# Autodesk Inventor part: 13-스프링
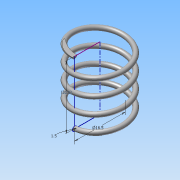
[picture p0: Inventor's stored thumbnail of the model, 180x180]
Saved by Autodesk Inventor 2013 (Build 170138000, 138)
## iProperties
Created: 2015-08
Part Number: 13-스프링
Material: 강철, 연강
Document SubType Name: Modeling
Designer: Administrator
Mass: 2.84502 g
Surface Area: 9.78731 cm^2
Volume: 0.361961 cm^3
Density: 7.86 g/cm^3
Author: Administrator
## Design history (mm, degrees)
sketch "스케치1"
  geometry: L1 (0, 0)-(8.25, 0); L2 (8.25, 0)-(8.25, 28); L3 (8.25, 28)-(0, 28); L4 (0, 28)-(0, 0); C1 r 0.75 at (8.25, 0); 1 further point
  constraints: 8 end point, 2 coincident, 2 parallel, 1 centre point, 1 horizontal, 1 perpendicular
  dimensions: "d0" = 16.5 diameter of L2 L4; "d2" = 28 distance of L1.end L2.end (derived); "d3" = 1.5 diameter of C1
feature "코일1" sketch "스케치1" pitch "d4" = 10; turns "d6" = 4; dims "d5" = 28 (= d2), "d7" = 0, angle "d8" = 90 deg, angle "d9" = 90 deg, "d10" = 0, "d11" = 0
feature "분할1"
node "작업 평면1"
feature "분할2"
node "솔리드1"
other parameters: "d12" = 90 deg
